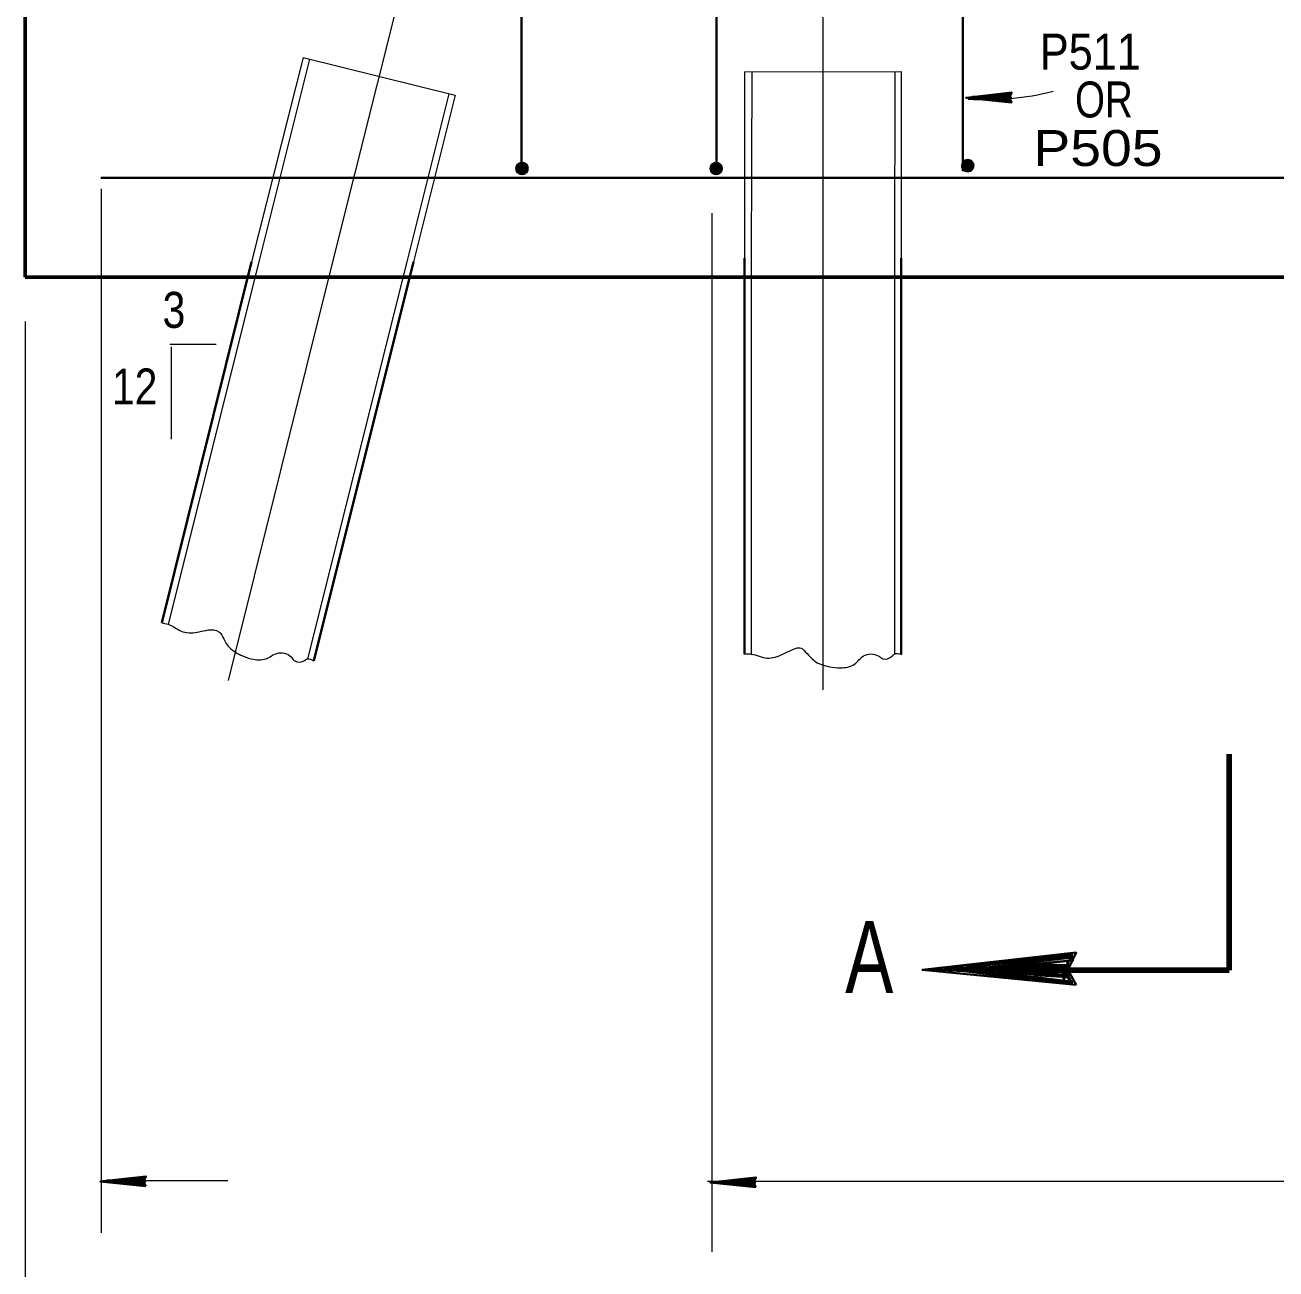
# Model space of a CAD drawing. Extents: x 3.64 to 6.84, y -0.8 to 1.19.
# Drawn here: x 3.9444 to 4.2342, y -0.3719 to -0.0837 of the extents above; entities that cross this region are included whole.
import ezdxf
from ezdxf.enums import TextEntityAlignment as Align

# ---------------------------------------------------------------- set-up
doc = ezdxf.new("R2010")
doc.units = 0
doc.header["$LTSCALE"] = 0.0033
doc.linetypes.add('DOT_DASHED', pattern=[7.7, 5, -1.2, 0.3, -1.2])
doc.linetypes.add('MEDIUM_DASHED', pattern=[4.5, 3, -1.5])
doc.layers.add('1', color=7, linetype='Continuous', lineweight=40)
doc.layers.add('5', color=7, linetype='MEDIUM_DASHED', lineweight=13)

msp = doc.modelspace()

# ---------------------------------------------------------------- linework, layer by layer
at = {"layer": '1'}
for p, q in [((4.059417, -0.00525), (4.059417, -0.117083)), ((4.104583, -0.00425), (4.104583, -0.11725)), ((4.161667, -0.0045), (4.161667, -0.1175)), ((4.058917, -0.11575), (4.058583, -0.11775)), ((4.059, -0.115833), (4.058667, -0.11775)), ((4.059083, -0.115833), (4.05875, -0.11775)), ((4.059167, -0.115833), (4.058833, -0.117833)), ((4.060333, -0.116), (4.058833, -0.115917)), ((4.059417, -0.115833), (4.059, -0.117833)), ((4.059583, -0.115917), (4.059167, -0.117833)), ((4.059667, -0.115917), (4.05925, -0.117833)), ((4.05975, -0.115917), (4.059333, -0.117917)), ((4.059833, -0.115917), (4.0595, -0.117917)), ((4.103917, -0.11575), (4.103583, -0.11775)), ((4.104, -0.115833), (4.103667, -0.11775)), ((4.104083, -0.115833), (4.10375, -0.11775)), ((4.104167, -0.115833), (4.103833, -0.117833)), ((4.105333, -0.116), (4.103833, -0.115917)), ((4.104417, -0.115833), (4.104, -0.117833)), ((4.104583, -0.115917), (4.104167, -0.117833)), ((4.104667, -0.115917), (4.10425, -0.117833)), ((4.10475, -0.115917), (4.104333, -0.117917)), ((4.104833, -0.115917), (4.1045, -0.117917)), ((4.162167, -0.115083), (4.161833, -0.117083)), ((4.16225, -0.115167), (4.161917, -0.117083)), ((4.162333, -0.115167), (4.162, -0.117083)), ((4.162417, -0.115167), (4.162083, -0.117167)), ((4.163583, -0.115333), (4.162083, -0.11525)), ((4.163583, -0.115417), (4.162083, -0.115333)), ((4.163583, -0.1155), (4.162083, -0.115417)), ((4.163583, -0.115583), (4.162083, -0.1155)), ((4.163583, -0.115667), (4.162083, -0.115583)), ((4.163583, -0.115833), (4.162083, -0.11575)), ((4.163583, -0.115917), (4.162083, -0.115833)), ((4.163583, -0.116), (4.162083, -0.115917)), ((4.162667, -0.115167), (4.16225, -0.117167)), ((4.162833, -0.11525), (4.162417, -0.117167)), ((4.162917, -0.11525), (4.1625, -0.117167)), ((4.163, -0.11525), (4.162583, -0.11725)), ((4.163083, -0.11525), (4.16275, -0.11725)), ((4.163167, -0.115333), (4.162833, -0.11725)), ((4.163333, -0.115333), (4.162917, -0.117333)), ((4.163417, -0.115333), (4.163, -0.117333)), ((4.1635, -0.115333), (4.163167, -0.117333)), ((4.163583, -0.115333), (4.16325, -0.117333)), ((4.16375, -0.115417), (4.163417, -0.117333)), ((4.06025, -0.117167), (4.05875, -0.117)), ((4.06025, -0.117333), (4.05875, -0.117167)), ((4.06025, -0.117417), (4.05875, -0.117333)), ((4.06025, -0.117417), (4.05875, -0.117333)), ((4.06025, -0.1175), (4.05875, -0.117417)), ((4.06025, -0.117583), (4.05875, -0.1175)), ((4.06025, -0.117667), (4.05875, -0.117583)), ((4.06025, -0.11775), (4.05875, -0.117667)), ((4.06025, -0.117833), (4.05875, -0.11775)), ((4.06025, -0.117917), (4.05875, -0.117833)), ((4.06025, -0.118083), (4.05875, -0.118)), ((4.060333, -0.116083), (4.058833, -0.116)), ((4.060333, -0.116167), (4.058833, -0.116083)), ((4.060333, -0.11625), (4.058833, -0.116167)), ((4.060333, -0.116333), (4.058833, -0.11625)), ((4.060333, -0.1165), (4.058833, -0.116417)), ((4.060333, -0.116583), (4.058833, -0.1165)), ((4.060333, -0.116667), (4.058833, -0.116583)), ((4.060333, -0.11675), (4.058833, -0.116667)), ((4.060333, -0.116833), (4.058833, -0.11675)), ((4.060333, -0.116917), (4.058833, -0.116833)), ((4.060333, -0.117), (4.058833, -0.116917)), ((4.059917, -0.116), (4.059583, -0.117917)), ((4.060083, -0.116), (4.059667, -0.118)), ((4.060167, -0.116), (4.05975, -0.118)), ((4.06025, -0.116), (4.059917, -0.118)), ((4.060333, -0.116), (4.06, -0.118)), ((4.0605, -0.116083), (4.060167, -0.118)), ((4.10525, -0.117167), (4.10375, -0.117)), ((4.10525, -0.117333), (4.10375, -0.117167)), ((4.10525, -0.117417), (4.10375, -0.117333)), ((4.10525, -0.117417), (4.10375, -0.117333)), ((4.10525, -0.1175), (4.10375, -0.117417)), ((4.10525, -0.117583), (4.10375, -0.1175)), ((4.10525, -0.117667), (4.10375, -0.117583)), ((4.10525, -0.11775), (4.10375, -0.117667)), ((4.10525, -0.117833), (4.10375, -0.11775)), ((4.10525, -0.117917), (4.10375, -0.117833)), ((4.10525, -0.118083), (4.10375, -0.118)), ((4.105333, -0.116083), (4.103833, -0.116)), ((4.105333, -0.116167), (4.103833, -0.116083)), ((4.105333, -0.11625), (4.103833, -0.116167)), ((4.105333, -0.116333), (4.103833, -0.11625)), ((4.105333, -0.1165), (4.103833, -0.116417)), ((4.105333, -0.116583), (4.103833, -0.1165)), ((4.105333, -0.116667), (4.103833, -0.116583)), ((4.105333, -0.11675), (4.103833, -0.116667)), ((4.105333, -0.116833), (4.103833, -0.11675)), ((4.105333, -0.116917), (4.103833, -0.116833)), ((4.105333, -0.117), (4.103833, -0.116917)), ((4.104917, -0.116), (4.104583, -0.117917)), ((4.105083, -0.116), (4.104667, -0.118)), ((4.105167, -0.116), (4.10475, -0.118)), ((4.10525, -0.116), (4.104917, -0.118)), ((4.105333, -0.116), (4.105, -0.118)), ((4.1055, -0.116083), (4.105167, -0.118)), ((4.1635, -0.1165), (4.162, -0.116333)), ((4.1635, -0.116667), (4.162, -0.1165)), ((4.1635, -0.11675), (4.162, -0.116667)), ((4.1635, -0.11675), (4.162, -0.116667)), ((4.1635, -0.116833), (4.162, -0.11675)), ((4.1635, -0.116917), (4.162, -0.116833)), ((4.1635, -0.117), (4.162, -0.116917)), ((4.1635, -0.117083), (4.162, -0.117)), ((4.1635, -0.117167), (4.162, -0.117083)), ((4.1635, -0.11725), (4.162, -0.117167)), ((4.1635, -0.117417), (4.162, -0.117333)), ((4.163583, -0.116083), (4.162083, -0.116)), ((4.163583, -0.116167), (4.162083, -0.116083)), ((4.163583, -0.11625), (4.162083, -0.116167)), ((4.163583, -0.116333), (4.162083, -0.11625))]:
    msp.add_line(p, q, dxfattribs=at)
at = {"layer": '1', "lineweight": 35}
for p, q in [((4.173, -0.1005), (4.162417, -0.1005)), ((4.17275, -0.101333), (4.164917, -0.100333)), ((4.17275, -0.101333), (4.164917, -0.1005)), ((4.17275, -0.1015), (4.164917, -0.100583)), ((4.17275, -0.1015), (4.164917, -0.100583)), ((4.17275, -0.101417), (4.164917, -0.100583)), ((4.17275, -0.099417), (4.165417, -0.10025)), ((4.17275, -0.099583), (4.165417, -0.100333)), ((4.17275, -0.099667), (4.165417, -0.1005)), ((4.172833, -0.099833), (4.1655, -0.100583)), ((4.187167, -0.298833), (4.162417, -0.301583)), ((4.187167, -0.299333), (4.162417, -0.302)), ((4.187167, -0.29975), (4.162417, -0.302583)), ((4.187417, -0.300333), (4.1625, -0.30275)), ((4.187917, -0.302583), (4.15225, -0.302583)), ((4.187167, -0.305333), (4.160583, -0.302)), ((4.187167, -0.305333), (4.160583, -0.302583)), ((4.187167, -0.306), (4.160583, -0.30275)), ((4.187167, -0.306), (4.160583, -0.30275)), ((4.187167, -0.305583), (4.160583, -0.30275)), ((3.972167, -0.3505), (3.964833, -0.351333)), ((3.972417, -0.351583), (3.961833, -0.351583)), ((3.972167, -0.352417), (3.964333, -0.351417)), ((3.972167, -0.352417), (3.964333, -0.351583)), ((3.972167, -0.352583), (3.964333, -0.351667)), ((3.972167, -0.352583), (3.964333, -0.351667)), ((3.972167, -0.3525), (3.964333, -0.351667)), ((3.972167, -0.350667), (3.964833, -0.351417)), ((3.972167, -0.35075), (3.964833, -0.351583)), ((3.97225, -0.350917), (3.964917, -0.351667)), ((4.11375, -0.351833), (4.103167, -0.351833)), ((4.1135, -0.352667), (4.105667, -0.351667)), ((4.1135, -0.352667), (4.105667, -0.351833)), ((4.1135, -0.352833), (4.105667, -0.351917)), ((4.1135, -0.352833), (4.105667, -0.351917)), ((4.1135, -0.35275), (4.105667, -0.351917)), ((4.1135, -0.35075), (4.106167, -0.351583)), ((4.1135, -0.350917), (4.106167, -0.351667)), ((4.1135, -0.351), (4.106167, -0.351833)), ((4.113583, -0.351167), (4.10625, -0.351917))]:
    msp.add_line(p, q, dxfattribs=at)
at = {"layer": '1', "lineweight": 13}
for p, q in [((3.962083, -0.121583), (3.962083, -0.3635)), ((4.1035, -0.12725), (4.1035, -0.367917)), ((3.944417, -0.152333), (3.944417, -0.41275)), ((3.978, -0.157583), (3.988667, -0.157583)), ((3.97825, -0.15825), (3.97825, -0.179583)), ((3.970583, -0.351417), (3.991417, -0.351417)), ((4.1025, -0.3515), (4.522667, -0.3515))]:
    msp.add_line(p, q, dxfattribs=at)
at = {"layer": '1', "lineweight": 60}
msp.add_line((4.694417, -0.142083), (3.944417, -0.142083), dxfattribs=at)
at = {"layer": '1', "lineweight": 90}
for p, q in [((4.223333, -0.252583), (4.223333, -0.302667)), ((4.223333, -0.302667), (4.181667, -0.302667))]:
    msp.add_line(p, q, dxfattribs=at)
at = {"layer": '1', "lineweight": 60}
msp.add_lwpolyline([(3.944417, -0.142083), (3.944417, -0.05875), (4.02775, -0.05875), (4.02775, 0.274583)], dxfattribs=at)
at = {"layer": '1', "lineweight": 35}
for points in [[(4.173, -0.101583), (4.162417, -0.1005), (4.173, -0.099333), (4.172417, -0.1005)], [(4.17225, -0.100583), (4.167583, -0.100667), (4.167583, -0.100583), (4.1685, -0.100583), (4.17225, -0.100667), (4.16925, -0.10075), (4.172417, -0.100833), (4.170167, -0.100917), (4.172417, -0.101), (4.168917, -0.10075), (4.16425, -0.100583), (4.165167, -0.100333), (4.163917, -0.100333), (4.17225, -0.100333), (4.169833, -0.100167), (4.172417, -0.100167), (4.167083, -0.100583), (4.172417, -0.099917)], [(4.187917, -0.306083), (4.15225, -0.302583), (4.187917, -0.298583), (4.186, -0.302583)], [(4.1855, -0.30275), (4.169667, -0.303083), (4.169667, -0.30275), (4.172667, -0.30275), (4.1855, -0.303083), (4.17525, -0.303333), (4.186, -0.30375), (4.17825, -0.303833), (4.186, -0.30425), (4.174167, -0.303333), (4.158333, -0.30275), (4.161417, -0.302), (4.15725, -0.302), (4.1855, -0.302), (4.177167, -0.3015), (4.186, -0.3015), (4.168, -0.30275), (4.186, -0.3005)], [(3.972417, -0.352667), (3.961833, -0.351583), (3.972417, -0.350417), (3.971833, -0.351583)], [(3.971667, -0.351667), (3.967, -0.35175), (3.967, -0.351667), (3.967917, -0.351667), (3.971667, -0.35175), (3.968667, -0.351833), (3.971833, -0.351917), (3.969583, -0.352), (3.971833, -0.352083), (3.968333, -0.351833), (3.963667, -0.351667), (3.964583, -0.351417), (3.963333, -0.351417), (3.971667, -0.351417), (3.96925, -0.35125), (3.971833, -0.35125), (3.9665, -0.351667), (3.971833, -0.351)], [(4.11375, -0.352917), (4.103167, -0.351833), (4.11375, -0.350667), (4.113167, -0.351833)], [(4.113, -0.351917), (4.108333, -0.352), (4.108333, -0.351917), (4.10925, -0.351917), (4.113, -0.352), (4.11, -0.352083), (4.113167, -0.352167), (4.110917, -0.35225), (4.113167, -0.352333), (4.109667, -0.352083), (4.105, -0.351917), (4.105917, -0.351667), (4.104667, -0.351667), (4.113, -0.351667), (4.110583, -0.3515), (4.113167, -0.3515), (4.107833, -0.351917), (4.113167, -0.35125)]]:
    msp.add_lwpolyline(points, close=True, dxfattribs=at)
for points in [[(4.17225, -0.100583), (4.172667, -0.101333), (4.172417, -0.101083), (4.17225, -0.10075), (4.172, -0.100833), (4.172167, -0.101167), (4.172333, -0.100417), (4.1725, -0.099917), (4.17275, -0.0995)], [(4.1855, -0.30275), (4.18675, -0.305333), (4.186, -0.3045), (4.1855, -0.303333), (4.1845, -0.30375), (4.185167, -0.304833), (4.185667, -0.30225), (4.18625, -0.3005), (4.187167, -0.29925)], [(3.971667, -0.351667), (3.972083, -0.352417), (3.971833, -0.352167), (3.971667, -0.351833), (3.971417, -0.351917), (3.971583, -0.35225), (3.97175, -0.3515), (3.971917, -0.351), (3.972167, -0.350583)], [(4.113, -0.351917), (4.113417, -0.352667), (4.113167, -0.352417), (4.113, -0.352083), (4.11275, -0.352167), (4.112917, -0.3525), (4.113083, -0.35175), (4.11325, -0.35125), (4.1135, -0.350833)]]:
    msp.add_lwpolyline(points, dxfattribs=at)
at = {"layer": '1'}
for points in [[(4.0595, -0.115583), (4.059833, -0.118167), (4.060333, -0.115833), (4.05925, -0.118167), (4.058833, -0.11575), (4.0585, -0.11775), (4.060583, -0.11775), (4.05825, -0.116833), (4.060833, -0.117083), (4.0585, -0.116083), (4.060833, -0.116417), (4.05825, -0.11725), (4.06, -0.115667), (4.060167, -0.118083), (4.058333, -0.116417), (4.06075, -0.1175), (4.060333, -0.115833), (4.058833, -0.11575), (4.05825, -0.116833), (4.0585, -0.11775), (4.05925, -0.118167), (4.060167, -0.118083), (4.06075, -0.1175), (4.059667, -0.116833), (4.05875, -0.118), (4.0585, -0.116083), (4.059667, -0.116833), (4.060167, -0.11575), (4.060833, -0.11675), (4.05975, -0.116833), (4.0585, -0.117667), (4.05975, -0.115667), (4.060083, -0.117), (4.060583, -0.11775)], [(4.1045, -0.115583), (4.104833, -0.118167), (4.105333, -0.115833), (4.10425, -0.118167), (4.103833, -0.11575), (4.1035, -0.11775), (4.105583, -0.11775), (4.10325, -0.116833), (4.105833, -0.117083), (4.1035, -0.116083), (4.105833, -0.116417), (4.10325, -0.11725), (4.105, -0.115667), (4.105167, -0.118083), (4.103333, -0.116417), (4.10575, -0.1175), (4.105333, -0.115833), (4.103833, -0.11575), (4.10325, -0.116833), (4.1035, -0.11775), (4.10425, -0.118167), (4.105167, -0.118083), (4.10575, -0.1175), (4.104667, -0.116833), (4.10375, -0.118), (4.1035, -0.116083), (4.104667, -0.116833), (4.105167, -0.11575), (4.105833, -0.11675), (4.10475, -0.116833), (4.1035, -0.117667), (4.10475, -0.115667), (4.105083, -0.117), (4.105583, -0.11775)], [(4.16275, -0.114917), (4.163083, -0.1175), (4.163583, -0.115167), (4.1625, -0.1175), (4.162083, -0.115083), (4.16175, -0.117083), (4.163833, -0.117083), (4.1615, -0.116167), (4.164083, -0.116417), (4.16175, -0.115417), (4.164083, -0.11575), (4.1615, -0.116583), (4.16325, -0.115), (4.163417, -0.117417), (4.161583, -0.11575), (4.164, -0.116833), (4.163583, -0.115167), (4.162083, -0.115083), (4.1615, -0.116167), (4.16175, -0.117083), (4.1625, -0.1175), (4.163417, -0.117417), (4.164, -0.116833), (4.162917, -0.116167), (4.162, -0.117333), (4.16175, -0.115417), (4.162917, -0.116167), (4.163417, -0.115083), (4.164083, -0.116083), (4.163, -0.116167), (4.16175, -0.117), (4.163, -0.115), (4.163333, -0.116333), (4.163833, -0.117083)], [(3.962, -0.119083), (4.271, -0.119083), (4.332917, -0.119083)]]:
    msp.add_lwpolyline(points, dxfattribs=at)
for centre in [(4.05955, -0.116917), (4.10455, -0.116917), (4.1628, -0.11625)]:
    msp.add_circle(centre, 0.00132, dxfattribs=at)
at = {"layer": '1', "lineweight": 13}
msp.add_arc((4.166958, -0.037788), 0.063175, 266.33195, 284.31953, dxfattribs=at)
at = {"layer": '5'}
for p, q in [((4.008833, -0.091167), (3.996917, -0.1385)), ((4.010333, -0.091583), (3.998583, -0.1385)), ((4.008833, -0.091167), (4.044083, -0.099917)), ((4.111083, -0.0945), (4.147417, -0.094417)), ((4.111083, -0.0945), (4.111083, -0.137667)), ((4.11275, -0.094417), (4.112667, -0.137667)), ((4.145917, -0.094417), (4.145833, -0.137667)), ((4.147417, -0.094417), (4.147417, -0.137667)), ((4.042583, -0.099583), (4.032833, -0.1385)), ((4.044083, -0.099917), (4.034417, -0.1385))]:
    msp.add_line(p, q, dxfattribs=at)
at = {"layer": '5', "linetype": 'Continuous', "lineweight": 35}
for p, q in [((3.996917, -0.1385), (3.976083, -0.222167)), ((4.034417, -0.1385), (4.011333, -0.231)), ((4.111083, -0.137667), (4.111083, -0.229417)), ((4.147417, -0.137667), (4.147417, -0.2295))]:
    msp.add_line(p, q, dxfattribs=at)
at = {"layer": '5', "linetype": 'Continuous'}
for p, q in [((3.998583, -0.1385), (3.977583, -0.2225)), ((4.032833, -0.1385), (4.009833, -0.2305)), ((4.112667, -0.137667), (4.112667, -0.229417)), ((4.145833, -0.137667), (4.145833, -0.229417))]:
    msp.add_line(p, q, dxfattribs=at)
at = {"layer": '5', "linetype": 'DOT_DASHED'}
for points in [[(4.12925, -0.054), (4.12925, -0.137667), (4.12925, -0.260083)], [(4.03625, -0.056333), (4.015667, -0.1385), (3.986333, -0.25625)]]:
    msp.add_lwpolyline(points, dxfattribs=at)
at = {"layer": '5', "linetype": 'Continuous'}
for points in [[(3.976083, -0.222167), (3.977583, -0.2225), (3.981, -0.22425), (3.98475, -0.22425), (3.986833, -0.223833), (3.989333, -0.22425), (3.98975, -0.224667), (3.990667, -0.226333), (3.9915, -0.227583), (3.994417, -0.229667), (3.996833, -0.2305), (4.00025, -0.2305), (4.00275, -0.22925), (4.006083, -0.230083), (4.006917, -0.231), (4.009, -0.231), (4.009833, -0.2305), (4.011333, -0.231)], [(4.111083, -0.229417), (4.112667, -0.229417), (4.116333, -0.230333), (4.12, -0.229417), (4.121917, -0.2285), (4.1245, -0.228167), (4.124917, -0.228583), (4.12625, -0.23), (4.127333, -0.231), (4.13075, -0.232333), (4.13325, -0.232583), (4.136583, -0.23175), (4.138667, -0.229833), (4.142083, -0.229833), (4.143167, -0.2305), (4.145167, -0.23), (4.145833, -0.229417), (4.147417, -0.2295)]]:
    msp.add_spline(points, degree=3, dxfattribs=at)

# ---------------------------------------------------------------- texts
at = {"layer": '1'}
for s, height, width, p in [('P511', 0.008334, 0.9, (4.1795, -0.094)), ('OR', 0.008334, 0.8, (4.187667, -0.105083)), ('P505', 0.008334, 1.15, (4.178, -0.116333)), ('A', 0.01667, 0.75, (4.134417, -0.307917))]:
    msp.add_text(s, height=height, dxfattribs=dict(at, width=width)).set_placement(p)
at = {"layer": '1', "width": 0.85}
msp.add_text('3', height=0.008334, dxfattribs=at).set_placement((3.978917, -0.153833), align=Align.CENTER)
msp.add_text('12', height=0.008334, dxfattribs=at).set_placement((3.975083, -0.171583), align=Align.RIGHT)

doc.saveas('drawing.dxf')
